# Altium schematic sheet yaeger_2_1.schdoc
size 127 x 101 mm
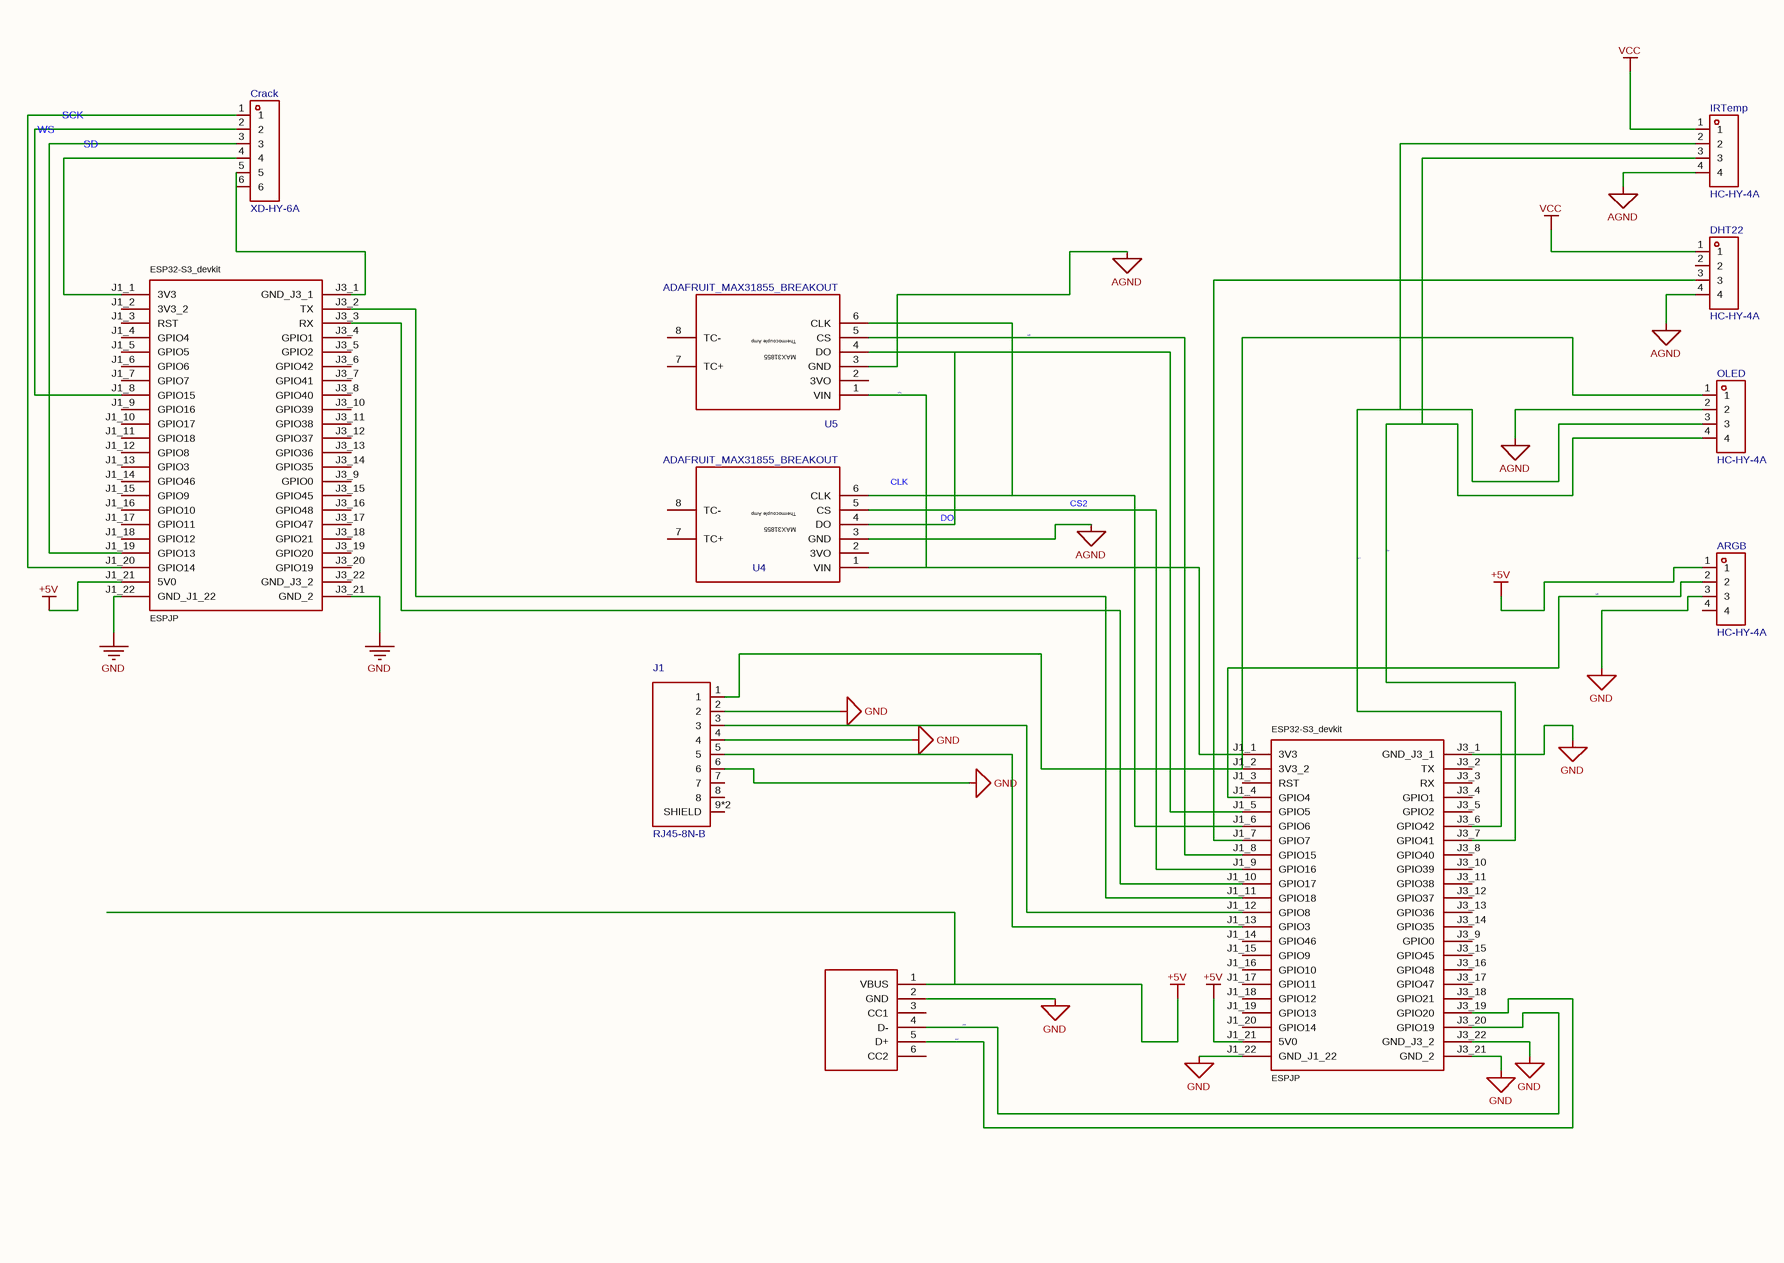
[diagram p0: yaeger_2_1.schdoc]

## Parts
ARGB  HC-HY-4A  [CONN-TH_4P-P2.00_HCTL_HC-HY-4A]
Crack  XD-HY-6A  [CONN-TH_6P-P2.00_HCTL_HC-HY-6A]
DHT22  HC-HY-4A  [CONN-TH_4P-P2.00_HCTL_HC-HY-4A]
IRTemp  HC-HY-4A  [CONN-TH_4P-P2.00_HCTL_HC-HY-4A]
J1  RJ45-8N-B  [TE_RJ45-8N-B]
OLED  HC-HY-4A  [CONN-TH_4P-P2.00_HCTL_HC-HY-4A]
U1  ESP32-S3-DEVKITM-1-N8  [MODULE_ESP32-S3-DEVKITM-1-N8]  (value not drawn)
U4  ADAFRUIT_MAX31855_BREAKOUT  [ADAFRUIT_MAX31855_BREAKOUT]
U5  ADAFRUIT_MAX31855_BREAKOUT  [ADAFRUIT_MAX31855_BREAKOUT]
U6  ESP32-S3-DEVKITM-1-N8  [MODULE_ESP32-S3-DEVKITM-1-N8]  (value not drawn)
U$1  USBC  [1X06]  (value not drawn)

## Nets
+5V: ARGB.1 U1.J1_21(5V0) U6.J1_21(5V0) U$1.1(VBUS)
AGND: DHT22.4 IRTemp.4 OLED.2 U4.3(GND) U5.3(GND)
GND: ARGB.3 J1.2 J1.4 J1.6 U1.J1_22(GND_J1_22) U1.J3_1(GND_J3_1) U1.J3_21(GND_2) U1.J3_22(GND_J3_2) U6.J1_22(GND_J1_22) U6.J3_21(GND_2) U$1.2(GND)
VCC: DHT22.1 IRTemp.1 J1.1 OLED.1 U1.J1_1(3V3) U1.J1_2(3V3_2) U4.1(VIN) U5.1(VIN)
CS2: U1.J1_9(GPIO16) U4.5(CS)
DA: IRTemp.3 OLED.4 U1.J3_7(GPIO41)
DO: U1.J1_5(GPIO5) U4.4(DO) U5.4(DO)
N$1: ARGB.2 U1.J1_4(GPIO4)
N$2: U1.J1_8(GPIO15) U5.5(CS)
N$4: U1.J3_20(GPIO19) U$1.4(D-)
N$7: U1.J3_19(GPIO20) U$1.5(D+)
SC: IRTemp.2 OLED.3 U1.J3_6(GPIO42)
NetCrack_1: Crack.1 U6.J1_20(GPIO14)
NetCrack_2: Crack.2 U6.J1_8(GPIO15)
NetCrack_3: Crack.3 U6.J1_19(GPIO13)
NetCrack_4: Crack.4 U6.J1_1(3V3)
NetCrack_5: Crack.5 Crack.6 U6.J3_1(GND_J3_1)
NetDHT22_3: DHT22.3 U1.J1_7(GPIO7)
NetJ1_3: J1.3 U1.J1_12(GPIO8)
NetJ1_5: J1.5 U1.J1_13(GPIO3)
NetU1_J1_6: U1.J1_6(GPIO6) U4.6(CLK) U5.6(CLK)
NetU1_J1_10: U1.J1_10(GPIO17) U6.J3_3(RX)
NetU1_J1_11: U1.J1_11(GPIO18) U6.J3_2(TX)

Not connected (* = marked no-connect by the designer): ARGB 4; DHT22 2; J1 7 8 9*2(SHIELD); U1 J1_3(RST) J1_14(GPIO46) J1_15(GPIO9) J1_16(GPIO10) J1_17(GPIO11) J1_18(GPIO12) J1_19(GPIO13) J1_20(GPIO14) J3_2(TX) J3_3(RX) J3_4(GPIO1) J3_5(GPIO2) J3_8(GPIO40) J3_9(GPIO0) J3_10(GPIO39) J3_11(GPIO38) J3_12(GPIO37) J3_13(GPIO36) J3_14(GPIO35) J3_15(GPIO45) J3_16(GPIO48) J3_17(GPIO47) J3_18(GPIO21); U4 2(3VO) 7(TC+) 8(TC-); U5 2(3VO) 7(TC+) 8(TC-); U6 J1_2(3V3_2) J1_3(RST) J1_4(GPIO4) J1_5(GPIO5) J1_6(GPIO6) J1_7(GPIO7) J1_9(GPIO16) J1_10(GPIO17) J1_11(GPIO18) J1_12(GPIO8) J1_13(GPIO3) J1_14(GPIO46) J1_15(GPIO9) J1_16(GPIO10) J1_17(GPIO11) J1_18(GPIO12) J3_4(GPIO1) J3_5(GPIO2) J3_6(GPIO42) J3_7(GPIO41) J3_8(GPIO40) J3_9(GPIO0) J3_10(GPIO39) J3_11(GPIO38) J3_12(GPIO37) J3_13(GPIO36) J3_14(GPIO35) J3_15(GPIO45) J3_16(GPIO48) J3_17(GPIO47) J3_18(GPIO21) J3_19(GPIO20) J3_20(GPIO19) J3_22(GND_J3_2); U$1 3(CC1) 6(CC2)

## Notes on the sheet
- Labels drawn without touching a wire or pin: CLK, SCK, SD, WS

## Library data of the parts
ARGB DHT22 OLED = HC-HY-4A: Pins Structure:1x4P Pitch:2mm Mounting Style:Direct Insert Reference Series:HY Number of Pins:4P Number of Rows:1 Number of PINs Per Row:4 Row Spacing:- Current Rating (Max):2A Contact Material:Brass Contact Plating:Tin Operating Temperature Range:-25℃~+8; Manufacturer: HCTL(华灿天禄); AddInBom: yes; ModelId: f44454f43a6b4f0dbbbf1e3fec5677df0819f05c4eef4c71ace90d822a990e87; ModelTransform: 393.7,200.787,0,180,0,0,0,-15.748,-118.11; Pins Structure: 1x4P; Pitch: 2mm; Reference Series: HY; Number of PINs Per Row: 4; Current Rating (Max): 2A; Rated Voltage (Max): 250V; Plastic Material: PA66; Z-Height of the Board: 7.8mm; X-Length of Bottom Edge on Board (Spacing Line): 10mm; Y-Width of Bottom Edge on Board: 5.1mm
Crack = XD-HY-6A: Pins Structure:1x6P Pitch:2mm Mounting Type:Through Hole Number of Pins:6P Number of Rows:1 Number of PINs Per Row:6 Current Rating:2A Operating Temperature:-25℃~+85℃ Operating Temperature:-25℃~+85℃ Voltage Rating:250V Plastic Material:PA66 Flame Retardan; Manufacturer: XUNDA(讯答); AddInBom: yes; ModelId: 346497cf354a4fb383f93bc6b2064f990819f05c4eef4c71ace90d822a990e87; ModelTransform: 551.18,200.787,0,0,0,0,0,16.142,-118.11; Pins Structure: 1x6P; Pitch: 2mm; Number of PINs Per Row: 6; Current Rating: 2A; Voltage Rating: 250V; Plastic Material: PA66; Flame Retardant Rating: UL94V-0; Z-Height of the Board: 7.8mm; X-Length of Bottom Edge on Board (Spacing Line): 13.5mm; Y-Width of Bottom Edge on Board: 6.2mm
IRTemp = HC-HY-4A: Pins Structure:1x4P Pitch:2mm Mounting Style:Direct Insert Reference Series:HY Number of Pins:4P Number of Rows:1 Number of PINs Per Row:4 Row Spacing:- Current Rating (Max):2A Contact Material:Brass Contact Plating:Tin Operating Temperature Range:-25℃~+8; Manufacturer: HCTL(华灿天禄); 3D Model: f44454f43a6b4f0dbbbf1e3fec5677df0819f05c4eef4c71ace90d822a990e87; 3D Model Transform: 393.7,200.787,0,180,0,0,0,-15.748,-118.11; Pins Structure: 1x4P; Pitch: 2mm; Reference Series: HY; Number of PINs Per Row: 4; Current Rating (Max): 2A; Rated Voltage (Max): 250V; Plastic Material: PA66; Z-Height of the Board: 7.8mm; X-Length of Bottom Edge on Board (Spacing Line): 10mm; Y-Width of Bottom Edge on Board: 5.1mm; AddInBom: yes
J1 = RJ45-8N-B_RJ45-8N-B_: UniqueId: 51bfc0e5166a1c40; MF: TE Connectivity; Package1: None; AddInBom: yes
U1 = ESP32-S3-DEVKITM-1-N8_ESPJP_: UniqueId: 1bdc0ab44f99f92d; MF: Espressif Systems; Package1: None; AddInBom: yes
U4 U5 = max_eagle_ADAFRUIT_MAX31855_BREAKOUT_: MPN: 269; AddInBom: yes
U6 = ESP32-S3-DEVKITM-1-N8_ESPJP_: MF: Espressif Systems; Package1: None; AddInBom: yes
U$1 = ESP32-S3-DEVKITM-1-N8_USBC_: UniqueId: 2f8b3f424349cf42; AddInBom: yes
